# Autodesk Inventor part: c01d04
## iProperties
Created: 2004-05
Part Number: c01d04
Document SubType Name: Modeling
Designer: CADCIM Technologies
Manufacturer: Standard
Standards Organization: Custom
Author: CADCIM Technologies
